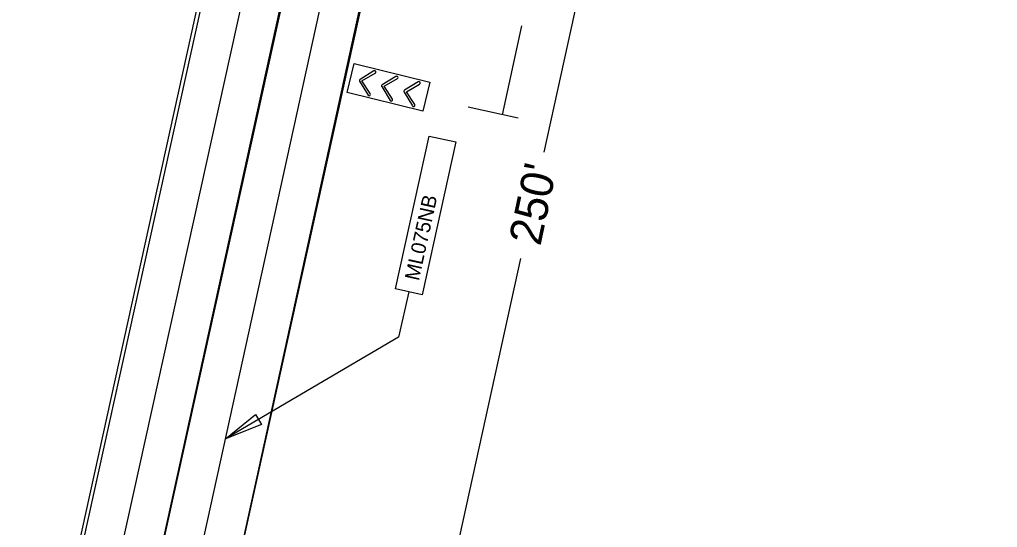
# Model space of a CAD drawing. Extents: x 14104283 to 14121738, y 8635219 to 8671666.
# Drawn here: x 14107527.6 to 14107828.5, y 8638000.8 to 8638157 of the extents above; entities that cross this region are included whole.
import ezdxf

# ---------------------------------------------------------------- set-up
doc = ezdxf.new("R2010")
doc.units = 0
for name, color, linetype in [('Default', 7, 'Continuous'), ('dsnPaintExistingBrokenLaneLineWhite', 7, 'Continuous'), ('dsnPaintExistingDoubleCenterYellow', 7, 'Continuous'), ('dsnPaintExistingEdgeLineRightWhite', 7, 'Continuous'), ('dsnStdLabel', 7, 'Continuous'), ('dsnStdLineWork', 7, 'Continuous'), ('Text', 7, 'Continuous')]:
    doc.layers.add(name, color=color, linetype=linetype)

msp = doc.modelspace()

# ---------------------------------------------------------------- linework, layer by layer
at = {"layer": 'Default'}
for points in [[(14107392.92, 8637186.73), (14107369.48, 8637191.91), (14107655.09, 8638485.14), (14107678.52, 8638479.96)], [(14107602.34, 8638246.31), (14107649.23, 8638236.01), (14107496.22, 8637543.21), (14107449.34, 8637553.51)], [(14107416.35, 8637181.55), (14107649.12, 8638235.55), (14107625.69, 8638240.73), (14107392.92, 8637186.73)]]:
    msp.add_lwpolyline(points, close=True, dxfattribs=at)
at = {"layer": 'dsnPaintExistingBrokenLaneLineWhite'}
for p, q in [((14107381.2, 8637189.32), (14107721.79, 8638731.54)), ((14107447.5, 8637375.04), (14107637.12, 8638238.2))]:
    msp.add_line(p, q, dxfattribs=at)
at = {"layer": 'dsnPaintExistingDoubleCenterYellow'}
msp.add_line((14107435.78, 8637377.61), (14107677.97, 8638480.08), dxfattribs=at)
at = {"layer": 'dsnPaintExistingEdgeLineRightWhite'}
for p, q in [((14107468.79, 8637415.99), (14107828.52, 8639053.57)), ((14107708.89, 8638734.37), (14107415.88, 8637407.61))]:
    msp.add_line(p, q, dxfattribs=at)
at = {"layer": 'dsnStdLabel'}
for p, q in [((14107689.02, 8638116.2), (14107712.3, 8638222.15)), ((14107676.19, 8638127.7), (14107682.21, 8638155.1)), ((14107681.08, 8638126.63), (14107665.62, 8638130.02)), ((14107658.66, 8637977.98), (14107681.84, 8638083.5))]:
    msp.add_line(p, q, dxfattribs=at)
msp.add_lwpolyline([(14107651.73, 8638128.86), (14107628.4, 8638134.52), (14107630.57, 8638143.44), (14107653.89, 8638137.78)], close=True, dxfattribs=at)
at = {"layer": 'dsnStdLineWork'}
for p, q in [((14107632.22, 8638138.01), (14107634.82, 8638133.75)), ((14107639.04, 8638136.36), (14107641.64, 8638132.1)), ((14107645.9, 8638134.69), (14107648.5, 8638130.44))]:
    msp.add_line(p, q, dxfattribs=at)
for points in [[(14107636.63, 8638141.18), (14107636.61, 8638141.17), (14107632.36, 8638138.58), (14107632.36, 8638138.58)], [(14107635.52, 8638134.18), (14107635.51, 8638134.2), (14107632.97, 8638138.13), (14107637.03, 8638140.47)], [(14107643.45, 8638139.53), (14107643.43, 8638139.52), (14107639.18, 8638136.93), (14107639.17, 8638136.93)], [(14107642.34, 8638132.53), (14107642.33, 8638132.55), (14107639.79, 8638136.48), (14107643.85, 8638138.81)], [(14107650.31, 8638137.87), (14107650.29, 8638137.86), (14107646.04, 8638135.26), (14107646.03, 8638135.26)], [(14107649.2, 8638130.86), (14107649.19, 8638130.88), (14107646.65, 8638134.81), (14107650.71, 8638137.15)]]:
    msp.add_lwpolyline(points, dxfattribs=at)
for centre, start, end in [((14107636.83, 8638140.83), 299.0054, 120.1646), ((14107643.65, 8638139.17), 299.0054, 120.1646), ((14107632.57, 8638138.23), 121.7557, 212.204), ((14107639.39, 8638136.58), 121.7557, 212.204), ((14107650.51, 8638137.51), 299.0054, 120.1646), ((14107635.17, 8638133.97), 211.0845, 31.2681), ((14107646.25, 8638134.91), 121.7557, 212.204), ((14107641.99, 8638132.31), 211.0845, 31.2681), ((14107648.85, 8638130.65), 211.0845, 31.2681)]:
    msp.add_arc(centre, 0.412, start, end, dxfattribs=at)
at = {"layer": 'Text'}
for points in [[(14107643.3, 8638074.15), (14107653.62, 8638121.14), (14107661.82, 8638119.34), (14107651.5, 8638072.35)], [(14107643.3, 8638074.15), (14107653.62, 8638121.14), (14107661.82, 8638119.34), (14107651.5, 8638072.35)], [(14107590.95, 8638028.05), (14107600.25, 8638035.55), (14107602.04, 8638032.49)]]:
    msp.add_lwpolyline(points, close=True, dxfattribs=at)
msp.add_lwpolyline([(14107647.4, 8638073.25), (14107644.24, 8638059.3), (14107590.95, 8638028.05)], dxfattribs=at)

# ---------------------------------------------------------------- texts
at = {"layer": 'dsnStdLabel'}
msp.add_text("250'", height=10, rotation=78.0531, dxfattribs=at).set_placement((14107687.85, 8638087.11))
at = {"layer": 'Text'}
msp.add_text('ML075NB', height=4.484, rotation=77.6078, dxfattribs=at).set_placement((14107650.46, 8638076.46))

doc.saveas('drawing.dxf')
